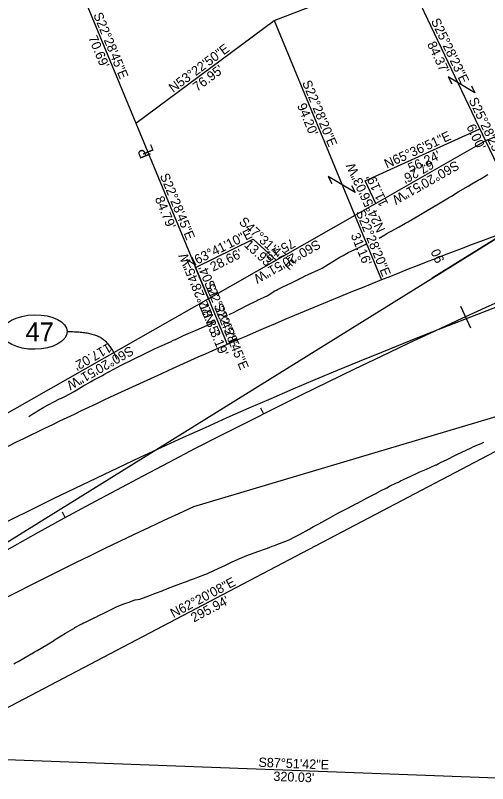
# Model space of a CAD drawing. Extents: x 1145508 to 2262867, y -3126236 to 2021677.
# Drawn here: x 1151327.6 to 1151538.5, y 2020168.5 to 2020511.6 of the extents above; entities that cross this region are included whole.
import ezdxf

# ---------------------------------------------------------------- set-up
doc = ezdxf.new("R2010")
doc.units = 0
for name, color, linetype in [('Default', 7, 'Continuous'), ('DSN_DRFT_Guideline-No-Plot', 7, 'Continuous'), ('DSN_RDWY_Alignment', 7, 'Continuous'), ('DSN_RDWY_Alignment Annotation', 7, 'Continuous'), ('DSN_RDWY_Const Limits', 7, 'Continuous'), ('DSN_ROW_Annotation', 7, 'Continuous'), ('DSN_ROW_Esmnt', 7, 'Continuous'), ('DSN_ROW_Line', 7, 'Continuous'), ('DSN_ROW_Line-Annotation', 7, 'Continuous'), ('DSN_ROW_Prop-Line', 7, 'Continuous'), ('DSN_ROW_Prop-Line-Annotation', 7, 'Continuous'), ('E_Const Align', 7, 'Continuous'), ('EX_QSECTION', 7, 'Continuous'), ('EX_ROW', 7, 'Continuous'), ('EX_ROW_ANNOT', 7, 'Continuous')]:
    doc.layers.add(name, color=color, linetype=linetype)

msp = doc.modelspace()

# ---------------------------------------------------------------- linework, layer by layer
at = {"layer": 'Default'}
msp.add_arc((1152351.97, 2018237.09), 2291.83, 105.0994, 122.23857, dxfattribs=at)
at = {"layer": 'DSN_RDWY_Alignment'}
msp.add_line((1151211.88, 2020206.81), (1151574.96, 2020432.19), dxfattribs=at)
at = {"layer": 'DSN_RDWY_Alignment Annotation'}
for p, q in [((1151574.96, 2020432.19), (1151513.79, 2020394.22)), ((1151526.42, 2020381.74), (1151530.84, 2020372.08)), ((1151437.14, 2020336.3), (1151438.49, 2020333.62)), ((1151348.46, 2020289.88), (1151349.9, 2020287.24))]:
    msp.add_line(p, q, dxfattribs=at)
at = {"layer": 'DSN_RDWY_Const Limits'}
for points in [[(1151490.1, 2020412.14), (1151492.57, 2020413.61), (1151493.54, 2020414.15), (1151493.54, 2020414.15), (1151493.55, 2020414.15), (1151493.56, 2020414.16), (1151494.52, 2020414.69), (1151495.74, 2020415.37), (1151497.06, 2020416.1), (1151498.98, 2020417.16), (1151501.86, 2020418.74), (1151503, 2020419.37), (1151503.13, 2020419.44), (1151503.45, 2020419.62), (1151507.88, 2020422.17), (1151512.26, 2020424.82), (1151512.59, 2020425.02), (1151516.65, 2020427.45), (1151518.08, 2020428.31), (1151520.37, 2020429.68), (1151521.05, 2020430.08), (1151522.03, 2020430.67), (1151522.37, 2020430.87), (1151525.45, 2020432.7), (1151529.84, 2020435.36), (1151531.47, 2020436.34), (1151534.26, 2020437.95), (1151535.19, 2020438.49), (1151538.68, 2020440.53)], [(1151423.13, 2020377.97), (1151425.55, 2020379.21), (1151426.7, 2020379.8), (1151427.19, 2020380.05), (1151427.9, 2020380.42), (1151431.23, 2020382.11), (1151435.31, 2020384.08), (1151435.8, 2020384.32), (1151440.38, 2020386.52), (1151443.26, 2020388.46), (1151444.18, 2020388.9), (1151444.74, 2020389.17), (1151444.93, 2020389.26), (1151446.45, 2020390), (1151449.31, 2020391.39), (1151450.67, 2020392.05), (1151453.87, 2020393.65), (1151454.72, 2020394.08), (1151455.68, 2020394.57), (1151457.07, 2020395.27), (1151458.43, 2020395.89), (1151463.05, 2020398.01), (1151464.61, 2020398.71), (1151467.5, 2020400.48), (1151471.28, 2020402.89), (1151471.56, 2020403.04), (1151471.84, 2020403.18), (1151472.53, 2020403.55), (1151474.02, 2020404.34), (1151476.31, 2020405.63), (1151480.91, 2020407.79), (1151483.78, 2020409.24), (1151484.63, 2020409.66)], [(1151333.63, 2020332.47), (1151335.85, 2020333.87), (1151335.98, 2020333.95), (1151337.77, 2020335.06), (1151340.31, 2020336.63), (1151344.78, 2020339.06), (1151347.37, 2020340.27), (1151348.26, 2020340.68), (1151349.05, 2020341.05), (1151349.39, 2020341.21), (1151349.73, 2020341.37), (1151353.84, 2020343.67), (1151356.96, 2020345.5), (1151358.23, 2020346.25), (1151359.1, 2020346.76), (1151361.21, 2020347.99), (1151362.62, 2020348.82), (1151365.59, 2020350.34), (1151366.5, 2020350.81), (1151367.14, 2020351.14), (1151371.59, 2020353.6), (1151374.84, 2020355.4), (1151375.14, 2020355.56), (1151376.07, 2020356), (1151376.1, 2020356.02), (1151376.64, 2020356.27), (1151377.66, 2020356.75), (1151380.68, 2020358.17), (1151385.24, 2020360.42), (1151385.94, 2020360.76), (1151386.24, 2020360.91), (1151389.81, 2020362.66), (1151392.4, 2020363.84), (1151392.81, 2020364.07), (1151393.24, 2020364.16), (1151394.47, 2020364.71), (1151395.85, 2020365.37), (1151396.88, 2020365.86), (1151397.51, 2020366.16), (1151397.84, 2020366.32), (1151399.05, 2020366.9), (1151402.67, 2020368.56), (1151403.69, 2020369.01), (1151405.78, 2020369.92), (1151408.41, 2020370.93), (1151413.05, 2020373.02), (1151414.39, 2020373.72), (1151415.09, 2020374.08), (1151415.75, 2020374.4), (1151415.77, 2020374.4), (1151416.8, 2020374.9)], [(1151326.84, 2020221.95), (1151327.66, 2020222.42), (1151328.86, 2020223.11), (1151331.31, 2020224.53), (1151333.12, 2020225.57), (1151334.71, 2020226.49), (1151334.83, 2020226.55), (1151336, 2020227.23), (1151337.29, 2020227.98), (1151337.38, 2020228.03), (1151341.61, 2020230.56), (1151345.03, 2020232.65), (1151345.06, 2020232.67), (1151345.52, 2020232.95), (1151345.81, 2020233.12), (1151348, 2020234.45), (1151350.02, 2020235.68), (1151354.1, 2020238.16), (1151354.23, 2020238.23), (1151356.98, 2020239.74), (1151357.35, 2020239.94), (1151357.61, 2020240.08), (1151358.07, 2020240.29), (1151358.59, 2020240.53), (1151362.85, 2020242.56), (1151363.03, 2020242.65), (1151363.56, 2020242.91), (1151364.87, 2020243.55), (1151367.46, 2020244.82), (1151370.93, 2020246.52), (1151371.53, 2020246.81), (1151371.88, 2020246.98), (1151372.72, 2020247.39), (1151373.06, 2020247.56), (1151376.45, 2020248.88), (1151378.45, 2020249.6), (1151380.98, 2020250.54), (1151381.14, 2020250.56), (1151383.25, 2020250.93), (1151386.01, 2020251.88), (1151390.63, 2020253.67), (1151393.22, 2020254.67), (1151394.11, 2020255.02), (1151394.9, 2020255.32), (1151395.24, 2020255.46), (1151395.59, 2020255.59), (1151399.87, 2020257.23), (1151403.16, 2020258.46), (1151404.51, 2020258.97), (1151405.43, 2020259.31), (1151407.66, 2020260.14), (1151409.15, 2020260.7), (1151412.19, 2020261.83), (1151413.12, 2020262.19), (1151413.76, 2020262.47), (1151418.21, 2020264.56), (1151421.46, 2020266.07), (1151421.76, 2020266.21), (1151422.67, 2020266.63), (1151422.69, 2020266.65), (1151423.21, 2020266.89), (1151424.2, 2020267.35), (1151427.12, 2020268.7), (1151431.66, 2020270.62), (1151432.37, 2020270.88), (1151432.67, 2020270.99), (1151436.3, 2020272.32), (1151438.9, 2020273.28), (1151439.33, 2020273.43), (1151439.72, 2020273.58), (1151440.94, 2020274.02), (1151442.34, 2020274.53), (1151443.38, 2020274.91), (1151444.02, 2020275.14), (1151444.36, 2020275.27), (1151445.59, 2020275.71), (1151449.22, 2020277.03), (1151450.18, 2020277.5), (1151452.14, 2020278.51), (1151454.51, 2020279.81), (1151458.8, 2020282.19), (1151460.07, 2020282.9), (1151460.74, 2020283.27), (1151461.36, 2020283.61), (1151461.38, 2020283.62), (1151463.09, 2020284.57), (1151465.79, 2020286.06), (1151467.14, 2020286.8), (1151467.39, 2020286.94), (1151470.59, 2020288.7), (1151471.7, 2020289.28), (1151472.17, 2020289.53), (1151472.86, 2020289.89), (1151476.06, 2020291.53), (1151479.94, 2020293.57), (1151480.4, 2020293.81), (1151484.75, 2020296.09), (1151487.69, 2020297.62), (1151488.57, 2020298.08), (1151489.1, 2020298.36), (1151489.28, 2020298.45), (1151490.73, 2020299.2), (1151493.46, 2020300.61), (1151494.75, 2020301.28), (1151497.85, 2020302.79), (1151498.69, 2020303.2), (1151499.62, 2020303.65), (1151500.97, 2020304.3), (1151502.28, 2020304.92), (1151506.7, 2020307.04), (1151508.19, 2020307.75), (1151511.24, 2020308.91), (1151515.15, 2020310.68), (1151515.44, 2020310.81), (1151515.71, 2020310.94), (1151516.38, 2020311.27), (1151517.84, 2020311.99), (1151520.11, 2020313.11), (1151524.52, 2020315.27), (1151527.31, 2020316.62), (1151528.93, 2020317.4), (1151531.16, 2020318.46), (1151532.27, 2020318.99), (1151533.37, 2020319.5), (1151535.89, 2020320.61), (1151536.87, 2020321.04), (1151536.87, 2020321.04)]]:
    msp.add_lwpolyline(points, dxfattribs=at)
at = {"layer": 'DSN_ROW_Esmnt'}
for p, q in [((1151483.83, 2020437.7), (1151535.05, 2020460.92)), ((1151535.05, 2020460.92), (1151537.63, 2020455.5)), ((1151488.54, 2020427.55), (1151483.83, 2020437.7)), ((1151408.09, 2020398.92), (1151433.77, 2020411.63)), ((1151433.77, 2020411.63), (1151444.05, 2020402.22)), ((1151413.84, 2020385.02), (1151408.09, 2020398.92))]:
    msp.add_line(p, q, dxfattribs=at)
at = {"layer": 'DSN_ROW_Line'}
for p, q in [((1151622.49, 2020491.4), (1151537.63, 2020455.5)), ((1151537.63, 2020455.5), (1151479.18, 2020422.22)), ((1151479.18, 2020422.22), (1151413.84, 2020385.02)), ((1151413.84, 2020385.02), (1151312.14, 2020327.13)), ((1151282.65, 2020180.85), (1151544.76, 2020318.25))]:
    msp.add_line(p, q, dxfattribs=at)
at = {"layer": 'DSN_ROW_Line-Annotation'}
msp.add_ellipse((1151336.24, 2020370.16), major_axis=(14.54, 0.23), ratio=0.529773, dxfattribs=at)
msp.add_open_spline([(1151350.78, 2020370.39), (1151360.25, 2020370.39), (1151369.52, 2020365.96), (1151372.91, 2020358.04)], degree=2, dxfattribs=at)
at = {"layer": 'DSN_ROW_Prop-Line'}
for p, q in [((1151443.17, 2020509.27), (1151501.35, 2020531.67)), ((1151501.35, 2020531.67), (1151537.63, 2020455.5)), ((1151354.39, 2020528.69), (1151381.42, 2020463.37)), ((1151381.42, 2020463.37), (1151443.17, 2020509.27)), ((1151443.17, 2020509.27), (1151479.18, 2020422.22)), ((1151381.42, 2020463.37), (1151413.84, 2020385.02)), ((1151537.63, 2020455.5), (1151555.48, 2020418.03)), ((1151479.18, 2020422.22), (1151491.09, 2020393.43)), ((1151413.84, 2020385.02), (1151421.04, 2020367.61)), ((1151421.04, 2020367.61), (1151422.26, 2020364.66))]:
    msp.add_line(p, q, dxfattribs=at)
at = {"layer": 'DSN_ROW_Prop-Line-Annotation'}
for p, q in [((1151532.88, 2020476.9), (1151520.91, 2020484.09)), ((1151520.91, 2020484.09), (1151522.52, 2020480.93)), ((1151531.27, 2020480.06), (1151532.88, 2020476.9)), ((1151479.35, 2020432.5), (1151467.38, 2020439.68)), ((1151467.38, 2020439.68), (1151468.99, 2020436.52)), ((1151477.74, 2020435.65), (1151479.35, 2020432.5))]:
    msp.add_line(p, q, dxfattribs=at)
at = {"layer": 'E_Const Align'}
msp.add_arc((1152722.75, 2017772.83), 2864.79, 104.86102, 121.82944, dxfattribs=at)
msp.add_arc((1152722.75, 2017772.83), 2864.79, 104.86102, 121.82944, dxfattribs=at)
at = {"layer": 'EX_QSECTION'}
msp.add_line((1151292.92, 2020180.46), (1151612.73, 2020168.52), dxfattribs=at)
at = {"layer": 'EX_ROW'}
msp.add_line((1151609.36, 2020352.37), (1151407.12, 2020292.12), dxfattribs=at)
for radius, start, end in [(2321.83, 110.06234, 111.76342), (2321.83, 111.76342, 113.60439), (2321.83, 113.60439, 116.43421), (2261.83, 114.69172, 120.60151)]:
    msp.add_arc((1152351.97, 2018237.09), radius, start, end, dxfattribs=at)

# ---------------------------------------------------------------- texts
at = {"layer": 'DSN_DRFT_Guideline-No-Plot'}
msp.add_text('+', height=0.1, rotation=69.2037, dxfattribs=at).set_placement((1151537.67, 2020455.45))
at = {"layer": 'DSN_RDWY_Alignment Annotation'}
msp.add_text('90', height=4.2, rotation=114.6342, dxfattribs=at).set_placement((1151519.37, 2020402.14))
at = {"layer": 'DSN_ROW_Annotation'}
for s, rotation, p in [('S22°28\'45"E', 292.4792, (1151362.33, 2020511.86)), ('S25°28\'23"E', 295.4731, (1151513.09, 2020509.1)), ("70.69'", 292.4792, (1151360.07, 2020501.61)), ('N53°22\'50"E', 36.6194, (1151398.07, 2020476.87)), ("84.37'", 295.4731, (1151511.38, 2020498.75)), ("76.95'", 36.6194, (1151408.8, 2020477.36)), ('S22°28\'20"E', 292.4722, (1151455.6, 2020481.58)), ('S25°28\'23"E', 295.4731, (1151529.95, 2020473.73)), ("94.20'", 292.4722, (1151453.35, 2020471.33)), ("6.00'", 295.4731, (1151528.96, 2020461.84)), ('N65°36\'51"E', 24.3859, (1151493.53, 2020443.09)), ("56.24'", 24.3859, (1151504.12, 2020441.3)), ('S60°20\'51"W', 209.6526, (1151524.29, 2020446.87)), ("67.26'", 209.6526, (1151512.97, 2020447.33)), ('N24°56\'03"W', 114.9342, (1151492.98, 2020415.87)), ('S22°28\'45"E', 292.4792, (1151392.05, 2020440.03)), ("11.19'", 114.9342, (1151494.25, 2020427.38)), ("84.79'", 292.4792, (1151389.8, 2020429.78)), ('S22°28\'20"E', 292.4722, (1151479.56, 2020423.66)), ('S47°31\'47"E', 317.5296, (1151427.15, 2020418.91)), ('N63°41\'10"E', 26.3138, (1151405.24, 2020398.52)), ("31.16'", 292.4722, (1151477.31, 2020413.41)), ("13.93'", 317.5296, (1151429.45, 2020408.67)), ('S60°20\'51"W', 209.6526, (1151462.4, 2020411.63)), ("75.19'", 209.6526, (1151451.07, 2020412.09)), ("28.66'", 26.3138, (1151415.88, 2020397.09)), ('N22°28\'45"W', 112.4792, (1151417.04, 2020374.94)), ("15.04'", 112.4792, (1151418.79, 2020386.39)), ('S22°28\'45"E', 292.4792, (1151411.86, 2020392.15)), ("18.85'", 292.4792, (1151409.61, 2020381.9)), ('S22°28\'45"E', 292.4792, (1151416.08, 2020381.96)), ("3.19'", 292.4792, (1151414.48, 2020370.14)), ("117.02'", 209.6526, (1151369.03, 2020365.39)), ('S60°20\'51"W', 209.6526, (1151378.88, 2020364.09)), ('N62°20\'08"E', 27.6644, (1151398.18, 2020242.43)), ("295.94'", 27.6644, (1151407.34, 2020240.45))]:
    msp.add_text(s, height=4.2, rotation=rotation, dxfattribs=at).set_placement(p)
at = {"layer": 'DSN_ROW_Line-Annotation'}
msp.add_text('47', height=8.5, dxfattribs=at).set_placement((1151332.15, 2020365.95))
at = {"layer": 'DSN_ROW_Prop-Line-Annotation'}
for s, p in [('L', (1151389.59, 2020450.77)), ('P', (1151388.27, 2020448.96))]:
    msp.add_text(s, height=5, rotation=112.6702, dxfattribs=at).set_placement(p)
at = {"layer": 'EX_ROW_ANNOT'}
for s, p in [('S87°51\'42"E', (1151436.11, 2020176.02)), ('S87°51\'42"E', (1151436.11, 2020176.02)), ("320.03'", (1151442.78, 2020169.76)), ("320.03'", (1151442.78, 2020169.76))]:
    msp.add_text(s, height=4.2, rotation=357.8615, dxfattribs=at).set_placement(p)

doc.saveas('drawing.dxf')
